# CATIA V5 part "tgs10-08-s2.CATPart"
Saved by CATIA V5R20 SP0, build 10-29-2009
Part number: TGS10-08-S2
Revision: 1
Definition: design
Nomenclature: TGS10-08-S2
Source: made
Description: NOT SPECIFIED
Bounding box of the stored display mesh (mm): x -22 to 0.8, y 0 to 10, z -4 to 4
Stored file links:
  C:\Users\Raffaele\Desktop\3D X SITO CF\I-MOLD\TGS-S2\tgs10-s2.step\tgs10-08-s2.CATPart
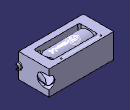
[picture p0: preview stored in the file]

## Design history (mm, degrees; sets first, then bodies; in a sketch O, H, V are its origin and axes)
Set1
  Line1 "LINE #4136": stored without definition
  DatumCurve1 "COMPOSITE_CURVE #4207"
  DatumCurve2 "COMPOSITE_CURVE #4258"
  DatumCurve3 "COMPOSITE_CURVE #4337"
  DatumCurve4 "COMPOSITE_CURVE #4380"
  DatumCurve5 "COMPOSITE_CURVE #4609"
  DatumCurve6 "COMPOSITE_CURVE #4751"
  DatumCurve7 "COMPOSITE_CURVE #4778"
  DatumCurve8 "COMPOSITE_CURVE #4836"
  DatumCurve9 "COMPOSITE_CURVE #4893"
  DatumCurve10 "COMPOSITE_CURVE #4922"
  DatumSurface1 "OPEN_SHELL #4126"
Body1 "MANIFOLD_SOLID_BREP #4127" (main body)
  Solid1: solid without history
